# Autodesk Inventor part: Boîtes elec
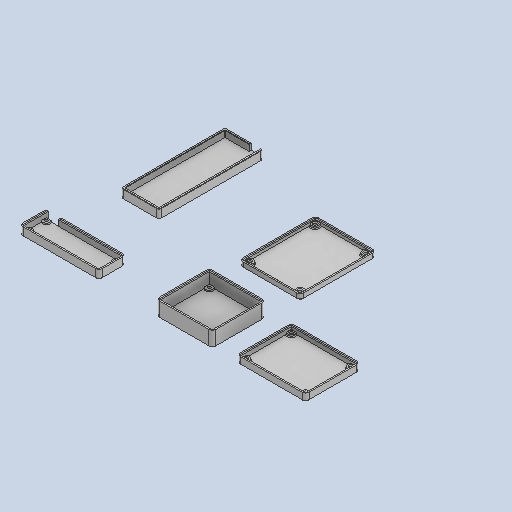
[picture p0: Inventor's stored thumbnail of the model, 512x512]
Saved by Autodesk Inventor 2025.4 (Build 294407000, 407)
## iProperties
Created: 2026-06
Part Number: Boîtes elec
Material: Generic
Document SubType Name: Modeling
Designer: AdminForWorker
Density: 1 g/cm^3
Appearance: Default
Title: Boîtes elec v6
Author: AdminForWorker
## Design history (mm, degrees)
feature "Box mot"
feature "Box Power"
feature "Box ESP"
feature "Box Jetson"
feature "Box Batterie"
body "Solid1"
body "Solid2"
body "Solid3"
body "Solid4"
body "Solid5"
